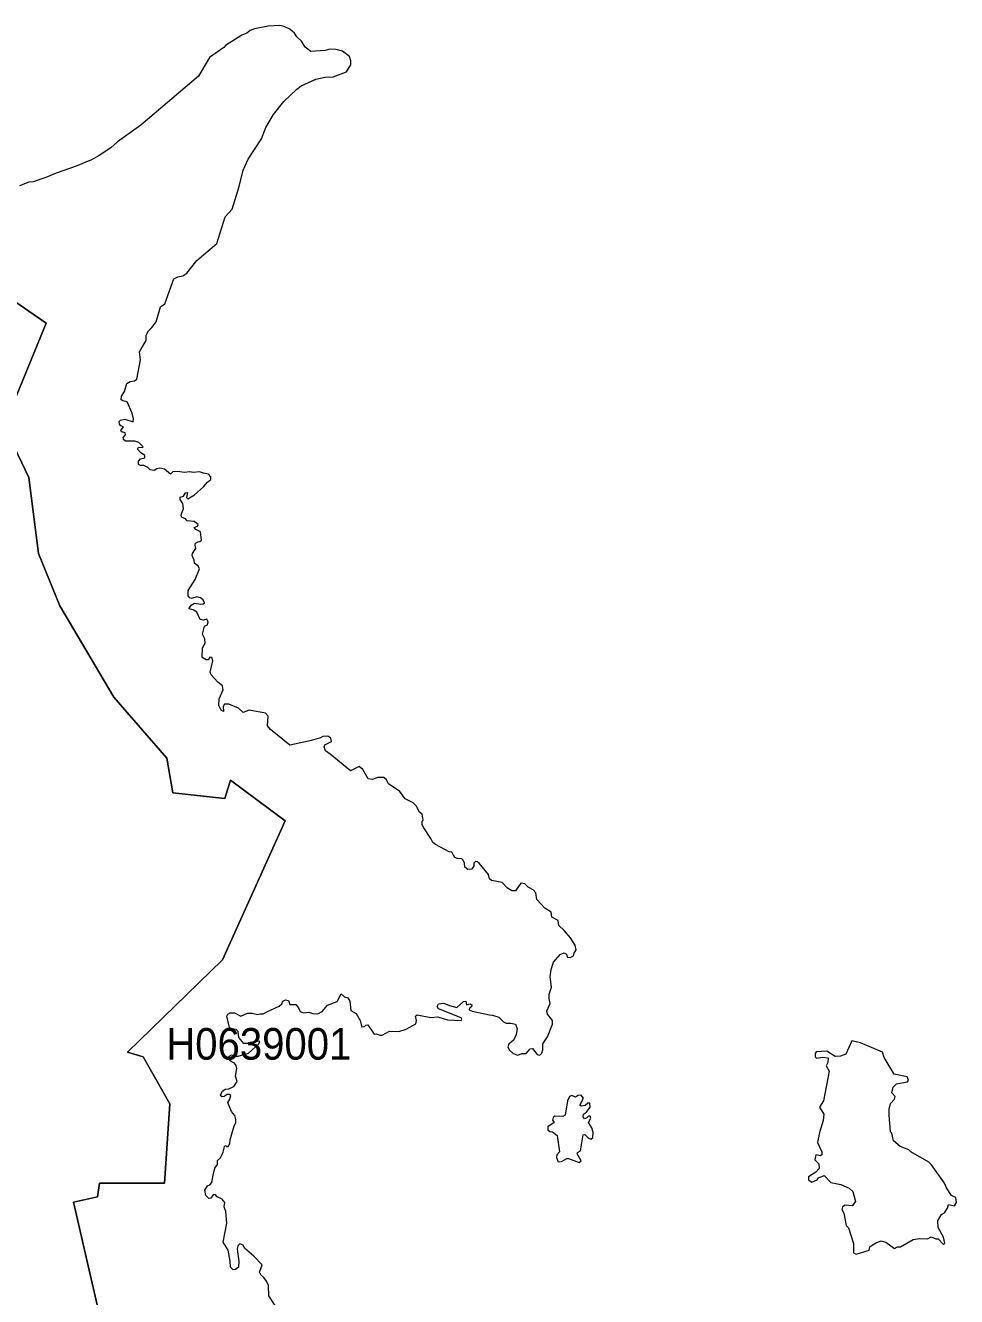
# Model space of a CAD drawing. Extents: x 369010 to 739155, y 6377141 to 6616555.
# Drawn here: x 438153 to 441101, y 6534686 to 6538712 of the extents above; entities that cross this region are included whole.
import ezdxf
from ezdxf.enums import TextEntityAlignment as Align

# ---------------------------------------------------------------- set-up
doc = ezdxf.new("R2010")
doc.units = 0
doc.header["$LTSCALE"] = 40
doc.layers.add('1', color=7, linetype='Continuous', lineweight=13)
doc.layers.add('2', color=7, linetype='Continuous')

msp = doc.modelspace()

# ---------------------------------------------------------------- linework, layer by layer
at = {"layer": '1'}
for points in [[(438497.89, 6537586.69), (438505.83, 6537592.15), (438516.92, 6537652.89), (438514.11, 6537678.54), (438517.91, 6537685.66), (438534.96, 6537714.12), (438534.96, 6537731.17), (438542.41, 6537744.74), (438553.17, 6537755.34), (438566.24, 6537773.54), (438580.64, 6537821.54), (438594.21, 6537830.97), (438622.35, 6537909.75), (438634.92, 6537916.54), (438651.64, 6537919.35), (438663.89, 6537928.12), (438695, 6537967.68), (438759.05, 6538021.47), (438784.87, 6538105.87), (438807.55, 6538130.04), (438829.39, 6538202.03), (438841.8, 6538254), (438858.52, 6538288.42), (438900.56, 6538353.3), (438914.13, 6538389.05), (438938.29, 6538430.26), (438970.57, 6538471.31), (439012.11, 6538511.03), (439026.34, 6538521.29), (439072.68, 6538541.81), (439102.14, 6538548.93), (439127.46, 6538549.42), (439169.83, 6538565.15), (439182.91, 6538587.32), (439183.24, 6538600.07), (439178.61, 6538613.97), (439156.92, 6538631.35), (439136.4, 6538636.48), (439116.54, 6538636.81), (439102.31, 6538632.51), (439056.96, 6538630.19), (439038.75, 6538643.59), (439026.51, 6538662.96), (439012.27, 6538676.03), (439004.83, 6538687.62), (438990.43, 6538700.69), (438972.22, 6538709.3), (438958.48, 6538712.44), (438921.41, 6538709.8), (438878.22, 6538701.52), (438864.31, 6538696.23), (438853.72, 6538687.95), (438838.33, 6538681.16), (438786.2, 6538648.73), (438781.06, 6538642.77), (438735.55, 6538610.33), (438700.3, 6538551.74), (438518.08, 6538396.99), (438443.93, 6538343.54), (438422.91, 6538324.83), (438386.17, 6538300.34), (438362.17, 6538286.77), (438313.02, 6538266.58), (438250.29, 6538244.07), (438217.85, 6538230.66), (438176.98, 6538216.76), (438163.9, 6538215.93), (438134.44, 6538204.02)], [(438429.04, 6534444.76), (438304.91, 6534985.29), (438381.04, 6535002.51), (438387.33, 6535046.03), (438592.72, 6535046.03), (438609.77, 6535297.27), (438525.69, 6535445.23), (438476.04, 6535460.79), (438776.27, 6535753.4), (438975.2, 6536192.81), (438802.58, 6536321.9), (438783.88, 6536264.31), (438619.04, 6536281.52), (438600.33, 6536391.91), (438432.51, 6536584.39), (438261.38, 6536874.03), (438194.52, 6537039.86), (438163.57, 6537280.84), (438085.78, 6537444.19), (438218.02, 6537769.07), (438028.19, 6537899.82)], [(438028.19, 6537899.82), (438218.02, 6537769.07), (438085.78, 6537444.19), (438163.57, 6537280.84), (438194.52, 6537039.86), (438261.38, 6536874.03), (438432.51, 6536584.39), (438600.33, 6536391.91), (438619.04, 6536281.52), (438783.88, 6536264.31), (438802.58, 6536321.9), (438975.2, 6536192.81), (438776.27, 6535753.4), (438476.04, 6535460.79), (438525.69, 6535445.23), (438609.77, 6535297.27), (438592.72, 6535046.03), (438387.33, 6535046.03), (438381.04, 6535002.51), (438304.91, 6534985.29), (438429.04, 6534444.76)], [(438707.75, 6536879.82), (438715.69, 6536880.65), (438719.66, 6536883.46), (438715.36, 6536892.89), (438706.59, 6536899.68), (438695.17, 6536903.15), (438678.12, 6536897.69), (438673.82, 6536899.18), (438668.19, 6536905.64), (438668.19, 6536923.02), (438690.04, 6536957.44), (438703.77, 6536991.04), (438699.8, 6537000.64), (438688.05, 6537008.08), (438687.22, 6537018.35), (438680.93, 6537033.08), (438681.6, 6537040.19), (438692.52, 6537056.08), (438689.71, 6537066.01), (438691.36, 6537072.3), (438698.48, 6537077.1), (438705.26, 6537078.26), (438710.39, 6537081.73), (438707.25, 6537108.38), (438692.19, 6537116.16), (438687.39, 6537122.61), (438697.32, 6537126.92), (438699.64, 6537132.05), (438686.56, 6537140.82), (438665.21, 6537143.14), (438660.08, 6537149.92), (438647.34, 6537155.38), (438646.18, 6537161.84), (438652.8, 6537182.36), (438650.81, 6537198.25), (438642.87, 6537210.5), (438642.54, 6537217.94), (438653.63, 6537221.92), (438659.09, 6537231.85), (438666.2, 6537232.67), (438662.73, 6537217.61), (438666.7, 6537212.81), (438688.05, 6537225.89), (438716.52, 6537250.55), (438729.59, 6537266.27), (438740.19, 6537273.88), (438739.85, 6537282.49), (438732.41, 6537290.93), (438716.52, 6537294.08), (438704.27, 6537298.38), (438684.08, 6537296.06), (438672.83, 6537298.71), (438655.78, 6537296.89), (438635.09, 6537299.54), (438619.7, 6537298.71), (438612.58, 6537291.26), (438593.22, 6537307.15), (438578.49, 6537309.8), (438568.39, 6537308.31), (438560.45, 6537302.35), (438548.2, 6537304.67), (438540.75, 6537311.78), (438527.18, 6537318.57), (438516.59, 6537318.24), (438510.63, 6537322.21), (438510.96, 6537332.47), (438516.92, 6537339.26), (438530.49, 6537343.06), (438530.82, 6537350.68), (438516.59, 6537360.11), (438507.82, 6537370.54), (438510.96, 6537376.33), (438523.71, 6537375.67), (438526.02, 6537377.99), (438511.79, 6537391.89), (438498.71, 6537395.86), (438469.42, 6537395.86), (438463.13, 6537400.99), (438461.97, 6537406.95), (438469.42, 6537415.22), (438468.59, 6537422.34), (438458.33, 6537425.49), (438455.35, 6537429.79), (438462.97, 6537440.88), (438455.35, 6537444.52), (438450.72, 6537449.65), (438449.89, 6537457.92), (438454.19, 6537461.9), (438467.6, 6537465.87), (438493.42, 6537457.26), (438494.91, 6537466.37), (438490.61, 6537484.07), (438474.39, 6537519.82), (438460.98, 6537522.97), (438455.85, 6537526.94), (438456.51, 6537538.69), (438466.11, 6537553.09), (438473.39, 6537578.41), (438484.48, 6537584.7), (438497.89, 6537586.69)], [(439744.96, 6535983.28), (439734.2, 6535993.21), (439721.95, 6535995.53), (439704.25, 6535971.7), (439693.16, 6535971.04), (439678.76, 6535980.14), (439661.88, 6535997.52), (439628.78, 6536003.81), (439621.99, 6536008.94), (439618.85, 6536023.34), (439589.22, 6536058.92), (439584.75, 6536063.72), (439577.64, 6536064.05), (439572.5, 6536058.92), (439572.17, 6536050.15), (439566.55, 6536039.89), (439553.47, 6536039.06), (439544.04, 6536046.18), (439543.21, 6536058.92), (439539.07, 6536068.35), (439534.27, 6536072.82), (439520.87, 6536073.48), (439512.92, 6536077.46), (439503.49, 6536093.67), (439495.05, 6536095.33), (439451.52, 6536117.84), (439442.42, 6536124.29), (439436.46, 6536137.37), (439414.61, 6536170.63), (439408.99, 6536180.9), (439408.66, 6536191.16), (439412.63, 6536195.46), (439408.66, 6536214.49), (439400.22, 6536220.12), (439389.95, 6536240.64), (439380.85, 6536249.75), (439355.2, 6536262.82), (439338.32, 6536285.83), (439302.24, 6536310.32), (439295.95, 6536323.39), (439288, 6536330.51), (439267.48, 6536330.18), (439251.59, 6536324.22), (439238.52, 6536326.54), (439221.31, 6536355.83), (439209.39, 6536365.76), (439182.08, 6536351.2), (439117.53, 6536403.83), (439102.97, 6536414.92), (439098.67, 6536427.99), (439101.31, 6536433.95), (439121.51, 6536444.54), (439120.02, 6536454.47), (439110.25, 6536461.59), (439094.86, 6536460.1), (439087.25, 6536456.46), (439057.29, 6536447.36), (439049.35, 6536445.04), (438990.43, 6536432.3), (438928.69, 6536482.61), (438919.59, 6536494.03), (438921.58, 6536524.65), (438912.47, 6536534.08), (438861.17, 6536544.01), (438842.3, 6536536.07), (438827.57, 6536550.3), (438796.29, 6536562.22), (438783.55, 6536562.22), (438778.91, 6536554.77), (438780.4, 6536539.71), (438772.46, 6536543.68), (438765.18, 6536558.24), (438766, 6536579.26), (438778.75, 6536608.56), (438776.27, 6536620.81), (438762.03, 6536632.39), (438740.68, 6536655.23), (438738.2, 6536663.67), (438746.47, 6536700.08), (438742.5, 6536710.67), (438736.88, 6536711.5), (438730.92, 6536703.56), (438725.46, 6536702.73), (438712.38, 6536710.67), (438713.54, 6536740.8), (438721.48, 6536756.19), (438720.99, 6536770.09), (438713.87, 6536784.82), (438719.99, 6536809.31), (438729.59, 6536814.44), (438731.58, 6536823.55), (438727.61, 6536831.49), (438716.52, 6536829.17), (438706.26, 6536831.16), (438696, 6536854), (438683.58, 6536861.61), (438670.18, 6536864.76), (438677.29, 6536876.18), (438688.05, 6536882.14), (438707.75, 6536879.82)], [(439152.46, 6535645.49), (439163.54, 6535635.23), (439173.47, 6535632.75), (439179.76, 6535622.15), (439183.4, 6535592.36), (439199.96, 6535582.6), (439213.03, 6535560.42), (439215.84, 6535547.68), (439218.49, 6535540.56), (439226.44, 6535542.05), (439230.41, 6535546.02), (439237.19, 6535546.85), (439256.56, 6535517.22), (439264.83, 6535518.05), (439275.26, 6535514.41), (439282.05, 6535514.74), (439305.55, 6535526.66), (439334.84, 6535525.5), (439358.51, 6535533.77), (439388.46, 6535550.49), (439391.11, 6535560.42), (439387.64, 6535574.16), (439393.1, 6535578.96), (439436.79, 6535569.85), (439458.97, 6535572.67), (439489.42, 6535562.74), (439532.12, 6535561.08), (439534.94, 6535564.72), (439532.12, 6535569.03), (439460.46, 6535597.49), (439456.16, 6535604.61), (439460.96, 6535613.38), (439477.17, 6535615.37), (439495.71, 6535607.92), (439518.55, 6535601.47), (439539.4, 6535621), (439547.02, 6535621.66), (439549, 6535610.57), (439559.6, 6535613.05), (439566.05, 6535609.91), (439565.55, 6535604.28), (439558.93, 6535599.48), (439558.11, 6535594.85), (439567.21, 6535590.38), (439622.16, 6535578.63), (439632.09, 6535577.8), (439651.28, 6535571.84), (439666.35, 6535556.78), (439674.62, 6535552.81), (439690.18, 6535552.81), (439704.74, 6535549.66), (439709.87, 6535534.27), (439706.73, 6535515.9), (439698.78, 6535499.02), (439683.72, 6535485.45), (439680.25, 6535476.84), (439684.22, 6535467.74), (439697.29, 6535455.82), (439711.69, 6535451.02), (439725.1, 6535456.65), (439738.17, 6535456.15), (439751.25, 6535471.21), (439758.37, 6535472.04), (439773.43, 6535453.01), (439781.37, 6535451.02), (439788.16, 6535457.81), (439790.8, 6535467.74), (439791.63, 6535487.1), (439805.87, 6535509.28), (439821.75, 6535549.66), (439821.59, 6535560.42), (439805.7, 6535581.27), (439803.38, 6535591.7), (439814.8, 6535615.04), (439811.66, 6535630.1), (439811.66, 6535643.84), (439818.44, 6535666.51), (439814.47, 6535698.62), (439817.78, 6535722.28), (439824.57, 6535745.29), (439845.92, 6535769.45), (439858.66, 6535775.41), (439866.11, 6535770.94), (439868.43, 6535761.84), (439877.53, 6535760.35), (439887.96, 6535765.81), (439889.94, 6535773.76), (439896.23, 6535784.84), (439893.09, 6535799.57), (439879.18, 6535822.41), (439858.99, 6535845.42), (439841.78, 6535862.13), (439840.12, 6535877.53), (439819.6, 6535888.28), (439817.62, 6535904.01), (439797.76, 6535916.75), (439771.94, 6535944.39), (439769.45, 6535965.08), (439760.35, 6535974.51), (439744.96, 6535983.28)], [(438810.36, 6534770.8), (438801.59, 6534779.08), (438800.76, 6534798.11), (438795.13, 6534833.69), (438779.24, 6534858.68), (438790.66, 6534918.76), (438787.52, 6534955.67), (438782.55, 6534970.73), (438783.88, 6534983.81), (438775.93, 6534994.4), (438760.05, 6535002.34), (438753.26, 6535009.95), (438746.97, 6535008.8), (438739.52, 6534997.71), (438733.07, 6534997.21), (438724.46, 6535006.81), (438721.32, 6535023.03), (438729.59, 6535037.59), (438736.71, 6535040.08), (438743, 6535047.52), (438746.97, 6535071.36), (438752.76, 6535092.71), (438761.04, 6535104.62), (438760.71, 6535117.2), (438770.14, 6535125.97), (438779.24, 6535143.35), (438781.56, 6535156.76), (438783.55, 6535162.71), (438788.35, 6535164.7), (438790.33, 6535160.4), (438794.3, 6535161.23), (438799.93, 6535169.83), (438801.42, 6535182.91), (438814.17, 6535226.93), (438818.8, 6535236.36), (438819.46, 6535247.45), (438816.32, 6535259.37), (438805.23, 6535272.78), (438793.31, 6535301.41), (438800.1, 6535312), (438803.57, 6535322.76), (438798.11, 6535326.73), (438791.33, 6535326.73), (438781.89, 6535319.61), (438774.28, 6535319.12), (438770.31, 6535325.07), (438776.76, 6535336.66), (438784.87, 6535342.95), (438796.62, 6535344.11), (438812.84, 6535351.22), (438823.6, 6535367.44), (438818.14, 6535384.49), (438822.11, 6535408.32), (438820.45, 6535417.76), (438814.5, 6535426.03), (438804.57, 6535430.5), (438798.61, 6535435.63), (438798.28, 6535448.21), (438805.06, 6535451.85), (438815.32, 6535448.21), (438826.74, 6535448.21), (438858.85, 6535457.81), (438891.79, 6535486.77), (438895.1, 6535494.22), (438880.37, 6535495.05), (438868.95, 6535488.26), (438844.78, 6535487.93), (438828.56, 6535506.8), (438826.58, 6535525.83), (438820.29, 6535532.62), (438806.72, 6535534.6), (438798.44, 6535538.91), (438790.17, 6535574.16), (438794.14, 6535581.27), (438800.93, 6535585.25), (438815.16, 6535584.92), (438835.02, 6535574.99), (438855.71, 6535583.76), (438870.77, 6535584.09), (438887.32, 6535579.29), (438896.42, 6535582.1), (438905.52, 6535582.1), (438919.76, 6535589.72), (438956, 6535606.6), (438964.44, 6535613.05), (438968.25, 6535622.15), (438975.86, 6535626.46), (438985.3, 6535624.14), (438989.77, 6535611.07), (439008.63, 6535611.07), (439017.9, 6535601.13), (439023.03, 6535588.89), (439033.13, 6535584.92), (439050.51, 6535587.23), (439063.08, 6535582.93), (439078.97, 6535582.1), (439092.05, 6535589.72), (439109.42, 6535609.41), (439139.55, 6535621.33), (439152.46, 6535645.49)], [(440783.17, 6534820.78), (440824.21, 6534833.03), (440827.03, 6534843.46), (440843.58, 6534855.21), (440862.44, 6534862.82), (440877.5, 6534858.52), (440904.81, 6534838.66), (440914.74, 6534843.46), (440924.01, 6534843.46), (440963.57, 6534866.96), (440983.43, 6534870.27), (441008.75, 6534869.77), (441020.66, 6534875.07), (441035.73, 6534869.44), (441042.84, 6534869.77), (441060.22, 6534851.4), (441064.03, 6534855.7), (441059.72, 6534874.57), (441042.84, 6534904.69), (441042.18, 6534926.21), (441053.93, 6534946.24), (441062.7, 6534951.86), (441072.63, 6534966.59), (441075.61, 6534977.85), (441094.98, 6534973.87), (441101.27, 6534984.14), (441098.45, 6534999.69), (441085.38, 6535006.64), (441069.16, 6535031.14), (441063.2, 6535045.54), (441022.32, 6535103.8), (441013.38, 6535112.4), (440956.28, 6535144.67), (440949.66, 6535151.13), (440923.18, 6535161.72), (440901.5, 6535179.93), (440896.04, 6535203.93), (440892.56, 6535207.9), (440887.77, 6535261.52), (440887.93, 6535279.56), (440892.56, 6535298.26), (440904.32, 6535311.83), (440906.8, 6535319.61), (440896.04, 6535332.03), (440900.34, 6535349.4), (440911.43, 6535360), (440946.19, 6535366.45), (440949, 6535371.75), (440944.53, 6535382.01), (440903.82, 6535390.94), (440871.55, 6535443.91), (440866.75, 6535460.62), (440797.4, 6535490.41), (440769.26, 6535495.87), (440750.89, 6535454), (440734.01, 6535447.38), (440716.96, 6535446.55), (440690.65, 6535463.44), (440656.72, 6535461.12), (440653.41, 6535456.48), (440653.41, 6535445.56), (440658.05, 6535441.26), (440676.42, 6535444.57), (440694.29, 6535442.25), (440693.96, 6535427.69), (440687.84, 6535417.26), (440698.1, 6535399.88), (440680.39, 6535306.04), (440667.64, 6535286.68), (440680.89, 6535264), (440678.57, 6535243.81), (440666.82, 6535206.08), (440660.86, 6535174.47), (440674.6, 6535145.17), (440674.6, 6535134.91), (440670.29, 6535132.43), (440655.23, 6535134.91), (440652.42, 6535119.35), (440664.67, 6535106.61), (440666.49, 6535091.88), (440655.23, 6535080.62), (440632.06, 6535066.06), (440632.06, 6535056.13), (440643.15, 6535049.01), (440660.2, 6535055.63), (440664.5, 6535062.25), (440681.88, 6535070.2), (440703.06, 6535048.02), (440735.17, 6535041.07), (440760.99, 6535030.15), (440772.41, 6535019.39), (440781.18, 6534987.78), (440770.75, 6534973.54), (440748.08, 6534976.36), (440739.64, 6534970.23), (440738.15, 6534961.79), (440744.27, 6534950.04), (440751.89, 6534911.81), (440759, 6534903.87), (440775.39, 6534854.22)], [(438943.59, 6534658.59), (438923.4, 6534688.71), (438922.57, 6534721.65), (438916.61, 6534735.05), (438908.01, 6534746.64), (438897.91, 6534755.24), (438893.44, 6534764.02), (438898.24, 6534775.1), (438902.54, 6534787.35), (438876.06, 6534814.66), (438846.44, 6534839.65), (438842.47, 6534849.08), (438831.71, 6534853.06), (438825.42, 6534847.6), (438823.43, 6534836.51), (438828.07, 6534797.28), (438827.41, 6534779.74), (438817.81, 6534772.29), (438810.36, 6534770.8)], [(440775.39, 6534854.22), (440775.39, 6534825.09), (440783.17, 6534820.78)]]:
    msp.add_lwpolyline(points, dxfattribs=at)
msp.add_lwpolyline([(439912.45, 6535323.75), (439903.35, 6535322.92), (439894.58, 6535317.46), (439883.16, 6535322.92), (439875.54, 6535320.27), (439869.58, 6535306.04), (439861.97, 6535260.86), (439854.36, 6535256.56), (439829.04, 6535258.05), (439823.91, 6535253.25), (439821.92, 6535244.64), (439827.38, 6535237.85), (439806.53, 6535224.45), (439806.86, 6535214.85), (439812.82, 6535209.72), (439821.92, 6535208.23), (439836.15, 6535196.31), (439843.77, 6535145.17), (439835.82, 6535135.74), (439834.17, 6535126.97), (439840.12, 6535113.56), (439850.39, 6535113.89), (439867.1, 6535123.82), (439872.56, 6535123.82), (439905.83, 6535110.75), (439912.95, 6535116.7), (439899.87, 6535138.55), (439901.03, 6535143.19), (439910.3, 6535148.32), (439918.74, 6535198.63), (439923.87, 6535199.46), (439935.29, 6535188.04), (439942.9, 6535185.22), (439949.19, 6535190.02), (439950.35, 6535205.75), (439946.05, 6535220.48), (439935.79, 6535237.52), (439942.9, 6535251.76), (439941.25, 6535257.71), (439935.79, 6535257.71), (439929.83, 6535250.93), (439923.54, 6535249.77), (439919.07, 6535256.06), (439919.9, 6535264), (439929.83, 6535270.29), (439940.92, 6535286.51), (439940.09, 6535299.26), (439933.3, 6535299.26), (439925.03, 6535291.64), (439913.11, 6535288.99), (439907.98, 6535292.47), (439919.57, 6535315.14)], close=True, dxfattribs=at)

# ---------------------------------------------------------------- texts
at = {"layer": '2', "width": 0.95}
msp.add_text('H0639001', height=100, dxfattribs=at).set_placement((438891.78, 6535436.77), align=Align.CENTER)

doc.saveas('drawing.dxf')
